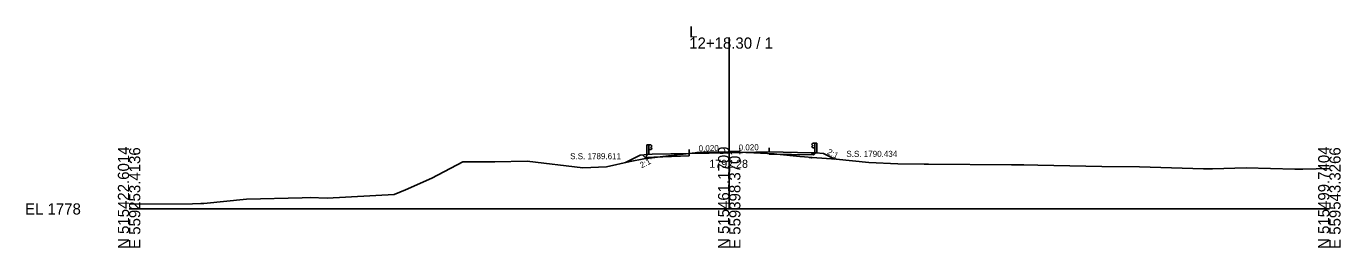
# Model space of a CAD drawing. Extents: x -26 to 1303, y -10 to 9545.
# Drawn here: x -25.7 to 302.8, y 4990.3 to 5045.6 of the extents above; entities that cross this region are included whole.
import ezdxf

# ---------------------------------------------------------------- set-up
doc = ezdxf.new("R2010")
doc.units = 0
for name, color, linetype in [('Exist Cross Section Cell', 7, 'Continuous'), ('Exist XS Center Line Elevation Label', 7, 'Continuous'), ('Exist XS Ground Line', 7, 'Continuous'), ('Prop XS Ditch Slope Text', 7, 'Continuous'), ('Prop XS Dump Level', 7, 'Continuous'), ('Prop XS EOT Tick Mark', 7, 'Continuous'), ('Prop XS Finish Grade', 7, 'Continuous'), ('Prop XS Finish Grade Earthwork', 7, 'Continuous'), ('Prop XS Finish Grade Paved Shoulder', 7, 'Continuous'), ('Prop XS Finish Grade Pavement', 7, 'Continuous'), ('Prop XS Guardrail', 7, 'Continuous'), ('Prop XS Pvmt Edge Slope', 7, 'Continuous'), ('Prop XS SE Text', 7, 'Continuous'), ('Prop XS SS Elevation Text', 7, 'Continuous'), ('Prop XS Subgrade Earthwork', 7, 'Continuous')]:
    doc.layers.add(name, color=color, linetype=linetype)

msp = doc.modelspace()

# ---------------------------------------------------------------- linework, layer by layer
at = {"layer": 'Exist Cross Section Cell'}
for p, q in [((150, 5000), (150, 5042.85)), ((0, 5000), (150, 5000)), ((150, 5000), (300, 5000))]:
    msp.add_line(p, q, dxfattribs=at)
at = {"layer": 'Exist XS Ground Line'}
for p, q in [((135.5, 5013.35), (141.48, 5014.04)), ((141.48, 5014.04), (141.93, 5014.11)), ((141.93, 5014.11), (143.47, 5014.15)), ((143.47, 5014.15), (150.12, 5014.28)), ((150.12, 5014.28), (156.14, 5014.05)), ((156.14, 5014.05), (161.27, 5013.75)), ((161.27, 5013.75), (161.89, 5013.72)), ((161.89, 5013.72), (167.63, 5013.12)), ((75.67, 5007.73), (83.41, 5011.78)), ((83.41, 5011.78), (91.39, 5011.8)), ((91.39, 5011.8), (99.52, 5011.92)), ((99.52, 5011.92), (113.38, 5010.27)), ((113.38, 5010.27), (119.29, 5010.56)), ((119.29, 5010.56), (125.28, 5011.87)), ((125.28, 5011.87), (128.69, 5012.55)), ((128.69, 5012.55), (135.5, 5013.35)), ((167.63, 5013.12), (168.79, 5013)), ((168.79, 5013), (170.7, 5012.83)), ((170.7, 5012.83), (176.76, 5012.41)), ((176.76, 5012.41), (184.88, 5011.62)), ((184.88, 5011.62), (192.13, 5011.29)), ((192.13, 5011.29), (198.74, 5011.15)), ((198.74, 5011.15), (199.82, 5011.15)), ((199.82, 5011.15), (220.55, 5011)), ((220.55, 5011), (223.63, 5011)), ((223.63, 5011), (227.17, 5010.96)), ((227.17, 5010.96), (243.16, 5010.64)), ((243.16, 5010.64), (252.51, 5010.54)), ((252.51, 5010.54), (268.56, 5010.01)), ((270.83, 5009.99), (279.24, 5010.23)), ((279.24, 5010.23), (291.36, 5009.92)), ((69.07, 5004.76), (75.67, 5007.73)), ((268.56, 5010.01), (270.83, 5009.99)), ((291.36, 5009.92), (293.37, 5009.95)), ((293.37, 5009.95), (300, 5010.11)), ((49.49, 5002.73), (66.27, 5003.6)), ((66.27, 5003.6), (69.07, 5004.76)), ((0, 5001.18), (15.83, 5001.27)), ((15.83, 5001.27), (17.97, 5001.35)), ((17.97, 5001.35), (18.65, 5001.37)), ((18.65, 5001.37), (29.35, 5002.48)), ((29.35, 5002.48), (43.3, 5002.81)), ((43.3, 5002.81), (45.28, 5002.87)), ((45.28, 5002.87), (49.49, 5002.73))]:
    msp.add_line(p, q, dxfattribs=at)
at = {"layer": 'Prop XS Dump Level'}
for p, q in [((140, 5013.84), (150, 5014.04)), ((150, 5014.04), (160, 5014.24))]:
    msp.add_line(p, q, dxfattribs=at)
at = {"layer": 'Prop XS EOT Tick Mark'}
for p, q in [((140, 5013.84), (140, 5014.84)), ((160, 5014.24), (160, 5015.24))]:
    msp.add_line(p, q, dxfattribs=at)
at = {"layer": 'Prop XS Finish Grade'}
for p, q in [((130.71, 5013.65), (129.69, 5013.57)), ((170.59, 5014.03), (171.61, 5013.99))]:
    msp.add_line(p, q, dxfattribs=at)
at = {"layer": 'Prop XS Finish Grade Earthwork'}
for p, q in [((127.71, 5013.41), (124.11, 5011.61)), ((129.69, 5013.57), (127.71, 5013.41)), ((171.61, 5013.99), (173.59, 5013.86)), ((173.59, 5013.86), (176.44, 5012.43))]:
    msp.add_line(p, q, dxfattribs=at)
at = {"layer": 'Prop XS Finish Grade Paved Shoulder'}
for p, q in [((140, 5013.84), (130.71, 5013.65)), ((160, 5014.24), (170.59, 5014.03))]:
    msp.add_line(p, q, dxfattribs=at)
at = {"layer": 'Prop XS Finish Grade Pavement'}
for p, q in [((140, 5013.84), (150, 5014.04)), ((150, 5014.04), (160, 5014.24))]:
    msp.add_line(p, q, dxfattribs=at)
at = {"layer": 'Prop XS Guardrail'}
for p, q in [((129.39, 5015.99), (129.89, 5015.99)), ((129.39, 5013.55), (129.39, 5015.99)), ((129.89, 5015.99), (130.39, 5015.99)), ((129.89, 5015.99), (129.89, 5013.59)), ((130.39, 5014.85), (129.89, 5014.85)), ((130.39, 5015.99), (130.68, 5015.79)), ((130.68, 5015.67), (130.39, 5015.47)), ((130.39, 5015.47), (130.39, 5015.37)), ((130.39, 5015.37), (130.68, 5015.17)), ((130.68, 5015.05), (130.39, 5014.85)), ((130.68, 5015.79), (130.71, 5015.73)), ((130.71, 5015.73), (130.68, 5015.67)), ((130.68, 5015.17), (130.71, 5015.11)), ((130.71, 5015.11), (130.68, 5015.05)), ((170.62, 5016.21), (170.59, 5016.15)), ((170.59, 5016.15), (170.62, 5016.09)), ((170.62, 5015.6), (170.59, 5015.54)), ((170.59, 5015.54), (170.62, 5015.48)), ((170.91, 5016.41), (170.62, 5016.21)), ((170.62, 5016.09), (170.91, 5015.89)), ((170.91, 5015.8), (170.62, 5015.6)), ((170.62, 5015.48), (170.91, 5015.28)), ((171.41, 5016.41), (170.91, 5016.41)), ((170.91, 5015.89), (170.91, 5015.8)), ((170.91, 5015.28), (171.41, 5015.28)), ((171.91, 5016.41), (171.41, 5016.41)), ((171.41, 5016.41), (171.41, 5013.91)), ((171.91, 5013.88), (171.91, 5016.41))]:
    msp.add_line(p, q, dxfattribs=at)
at = {"layer": 'Prop XS Pvmt Edge Slope'}
for p, q in [((129.69, 5013.57), (129, 5012.89)), ((170.59, 5014.03), (171.12, 5013.49))]:
    msp.add_line(p, q, dxfattribs=at)
at = {"layer": 'Prop XS Subgrade Earthwork'}
for p, q in [((129, 5012.89), (128.42, 5013.47)), ((140, 5013.3), (140, 5013.87)), ((160, 5013.7), (160, 5013.83)), ((160, 5013.7), (171.12, 5013.49)), ((171.12, 5013.49), (171.61, 5013.98)), ((140, 5013.3), (129, 5012.89))]:
    msp.add_line(p, q, dxfattribs=at)

# ---------------------------------------------------------------- texts
at = {"layer": 'Exist Cross Section Cell'}
for s, p in [('12+18.30 / 1', (140, 5040.05)), ('L', (140, 5042.85)), ('EL 1778', (-26, 4998.6))]:
    msp.add_text(s, height=2.8, dxfattribs=at).set_placement(p)
for s, p in [('N 515422.6014', (0, 4990)), ('E 559253.4136', (2.8, 4990)), ('N 515461.1709', (150, 4990)), ('E 559398.3701', (152.8, 4990)), ('N 515499.7404', (300, 4990)), ('E 559543.3266', (302.8, 4990))]:
    msp.add_text(s, height=2.8, rotation=90, dxfattribs=at).set_placement(p)
at = {"layer": 'Exist XS Center Line Elevation Label'}
msp.add_text('1792.28', height=2, dxfattribs=at).set_placement((145.02, 5010.28))
at = {"layer": 'Prop XS Ditch Slope Text'}
for rotation, p in [(333.4349, (174.34, 5013.77)), (26.5651, (128.11, 5010.14))]:
    msp.add_text('2:1', height=1.5, rotation=rotation, dxfattribs=at).set_placement(p)
at = {"layer": 'Prop XS Dump Level'}
for s, height, p in [('Case1', 0.04, (137, 5013.56)), ('Case1', 0.04, (163, 5014.08)), ('Eop', 0.3, (130, 5012.4)), ('Eop', 0.3, (170, 5012.59))]:
    msp.add_text(s, height=height, dxfattribs=at).set_placement(p)
at = {"layer": 'Prop XS SE Text'}
for p in [(142.38, 5014.38), (152.38, 5014.58)]:
    msp.add_text('0.020', height=1.5, rotation=1.1458, dxfattribs=at).set_placement(p)
at = {"layer": 'Prop XS SS Elevation Text'}
for s, p in [('S.S. 1789.611', (110.24, 5012.43)), ('S.S. 1790.434', (179.28, 5013.02))]:
    msp.add_text(s, height=1.5, dxfattribs=at).set_placement(p)

doc.saveas('drawing.dxf')
